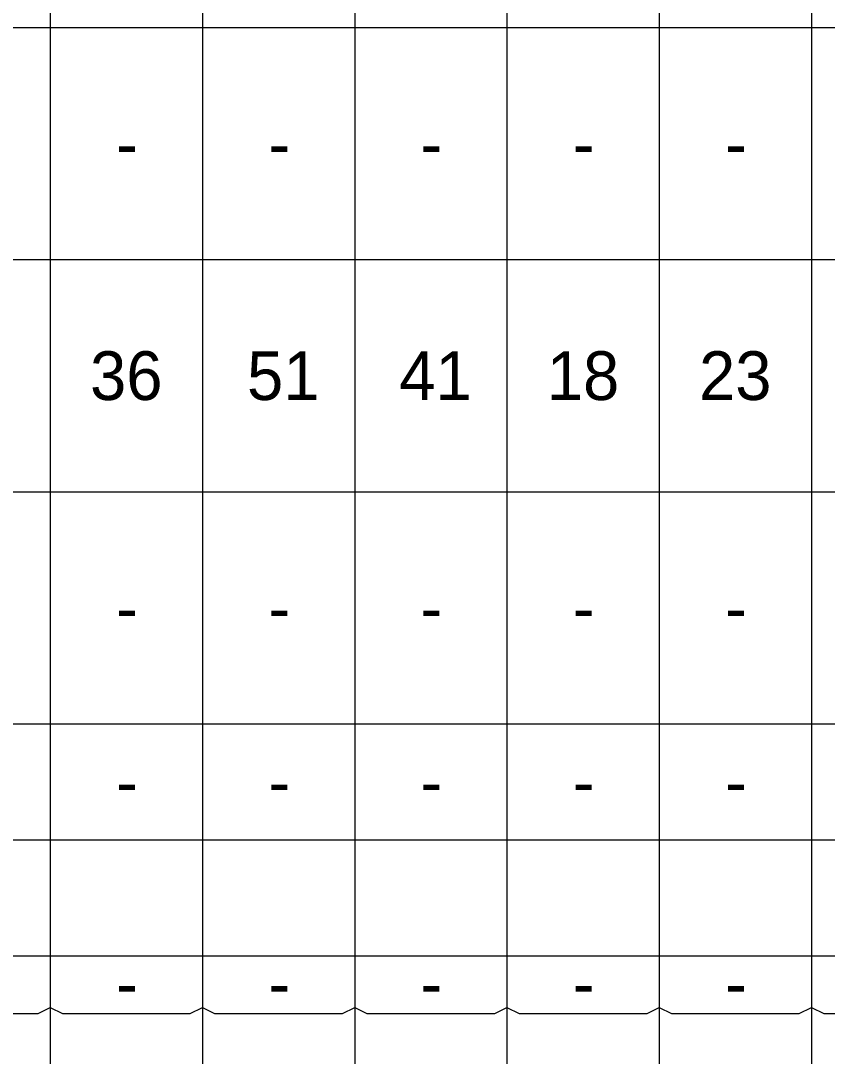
# Model space of a CAD drawing. Extents: x 0 to 0.833, y -0.323 to 0.608.
# Drawn here: x 0.6168 to 0.7272, y 0.2085 to 0.3502 of the extents above; entities that cross this region are included whole.
import ezdxf

# ---------------------------------------------------------------- set-up
doc = ezdxf.new("R2010")
doc.units = 0

msp = doc.modelspace()

# ---------------------------------------------------------------- linework, layer by layer
for points in [[(0.6625, 0.55417), (0.6625, -0.28575)], [(0.725, 0.55417), (0.725, -0.28575)], [(0.62083, 0.54167), (0.62083, -0.28575)], [(0.64167, 0.54167), (0.64167, -0.28575)], [(0.68333, 0.54167), (0.68333, -0.28575)], [(0.70417, 0.54167), (0.70417, -0.28575)], [(0.725, 0.54167), (0.725, -0.28575)], [(0.6, 0.34925), (0.62083, 0.34925)], [(0.62083, 0.34925), (0.64167, 0.34925)], [(0.64167, 0.34925), (0.6625, 0.34925)], [(0.6625, 0.34925), (0.68333, 0.34925)], [(0.68333, 0.34925), (0.70417, 0.34925)], [(0.70417, 0.34925), (0.725, 0.34925)], [(0.725, 0.34925), (0.75, 0.34925)], [(0.6, 0.3175), (0.62083, 0.3175)], [(0.62083, 0.3175), (0.64167, 0.3175)], [(0.64167, 0.3175), (0.6625, 0.3175)], [(0.6625, 0.3175), (0.68333, 0.3175)], [(0.68333, 0.3175), (0.70417, 0.3175)], [(0.70417, 0.3175), (0.725, 0.3175)], [(0.725, 0.3175), (0.75, 0.3175)], [(0.6, 0.28575), (0.62083, 0.28575)], [(0.62083, 0.28575), (0.64167, 0.28575)], [(0.64167, 0.28575), (0.6625, 0.28575)], [(0.6625, 0.28575), (0.68333, 0.28575)], [(0.68333, 0.28575), (0.70417, 0.28575)], [(0.70417, 0.28575), (0.725, 0.28575)], [(0.725, 0.28575), (0.75, 0.28575)], [(0.6, 0.254), (0.62083, 0.254)], [(0.62083, 0.254), (0.64167, 0.254)], [(0.64167, 0.254), (0.6625, 0.254)], [(0.6625, 0.254), (0.68333, 0.254)], [(0.68333, 0.254), (0.70417, 0.254)], [(0.70417, 0.254), (0.725, 0.254)], [(0.725, 0.254), (0.75, 0.254)], [(0.6, 0.23812), (0.62083, 0.23812)], [(0.62083, 0.23812), (0.64167, 0.23812)], [(0.64167, 0.23812), (0.6625, 0.23812)], [(0.6625, 0.23812), (0.68333, 0.23812)], [(0.68333, 0.23812), (0.70417, 0.23812)], [(0.70417, 0.23812), (0.725, 0.23812)], [(0.725, 0.23812), (0.75, 0.23812)], [(0.6, 0.22225), (0.62083, 0.22225)], [(0.62083, 0.22225), (0.64167, 0.22225)], [(0.64167, 0.22225), (0.6625, 0.22225)], [(0.6625, 0.22225), (0.68333, 0.22225)], [(0.68333, 0.22225), (0.70417, 0.22225)], [(0.70417, 0.22225), (0.725, 0.22225)], [(0.725, 0.22225), (0.75, 0.22225)], [(0.6, 0.21519), (0.60167, 0.21437), (0.61917, 0.21437), (0.62083, 0.21519)], [(0.62083, 0.21519), (0.6225, 0.21437), (0.64, 0.21437), (0.64167, 0.21519)], [(0.64167, 0.21519), (0.64333, 0.21437), (0.66083, 0.21437), (0.6625, 0.21519)], [(0.6625, 0.21519), (0.66417, 0.21437), (0.68167, 0.21437), (0.68333, 0.21519)], [(0.68333, 0.21519), (0.685, 0.21437), (0.7025, 0.21437), (0.70417, 0.21519)], [(0.70417, 0.21519), (0.70583, 0.21437), (0.72333, 0.21437), (0.725, 0.21519)], [(0.725, 0.21519), (0.72667, 0.21437), (0.74833, 0.21437), (0.75, 0.21519)]]:
    msp.add_lwpolyline(points)

# ---------------------------------------------------------------- texts
for s, height, p in [('-', 0.00667, (0.62984, 0.33004)), ('-', 0.00667, (0.65068, 0.33004)), ('-', 0.00667, (0.67151, 0.33004)), ('-', 0.00667, (0.69234, 0.33004)), ('-', 0.00667, (0.71318, 0.33004)), ('36', 0.006667, (0.62628, 0.29829)), ('51', 0.006667, (0.64776, 0.29829)), ('41', 0.006667, (0.66859, 0.29829)), ('18', 0.006667, (0.68878, 0.29829)), ('23', 0.006667, (0.70961, 0.29829)), ('-', 0.00667, (0.62984, 0.26654)), ('-', 0.00667, (0.65068, 0.26654)), ('-', 0.00667, (0.67151, 0.26654)), ('-', 0.00667, (0.69234, 0.26654)), ('-', 0.00667, (0.71318, 0.26654)), ('-', 0.00667, (0.62984, 0.24273)), ('-', 0.00667, (0.65068, 0.24273)), ('-', 0.00667, (0.67151, 0.24273)), ('-', 0.00667, (0.69234, 0.24273)), ('-', 0.00667, (0.71318, 0.24273)), ('-', 0.00667, (0.62984, 0.21517)), ('-', 0.00667, (0.65068, 0.21517)), ('-', 0.00667, (0.67151, 0.21517)), ('-', 0.00667, (0.69234, 0.21517)), ('-', 0.00667, (0.71318, 0.21517))]:
    msp.add_text(s, height=height).set_placement(p)

doc.saveas('drawing.dxf')
